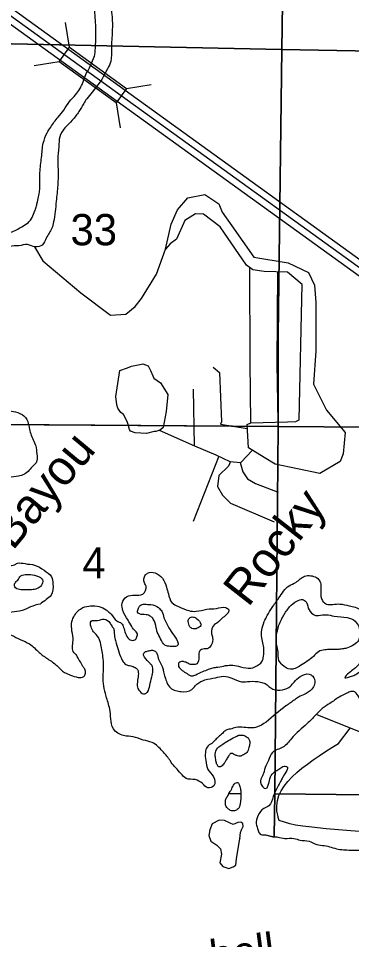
# Model space of a CAD drawing. Extents: x 380424 to 701066, y 1117407 to 1412949.
# Drawn here: x 458914 to 463713, y 1324590 to 1337847 of the extents above; entities that cross this region are included whole.
import ezdxf

# ---------------------------------------------------------------- set-up
doc = ezdxf.new("R2010")
doc.units = 0
for name, color, linetype in [('Bayou and Harbor etc Text', 7, 'Continuous'), ('Bridges and Drawbridges State Highways', 7, 'Continuous'), ('Cities Incorporated Area', 7, 'Continuous'), ('Islands', 7, 'Continuous'), ('Lakes and Ponds', 7, 'Continuous'), ('Narrow Canals', 7, 'Continuous'), ('Narrow River Creek and Branch and Slough', 7, 'Continuous'), ('Narrow River Creek and Branch and Slough Text', 7, 'Continuous'), ('Section Lines', 7, 'Continuous'), ('Section Numbers', 7, 'Continuous'), ('State Roads Related Text', 7, 'Continuous'), ('State Route Divided Highway Outline and Fill', 7, 'Continuous'), ('State Routes Highway Center Lines', 7, 'Continuous'), ('Township  and Range lines', 7, 'Continuous'), ('Wide Rivers and Canals', 7, 'Continuous')]:
    doc.layers.add(name, color=color, linetype=linetype)

msp = doc.modelspace()

# ---------------------------------------------------------------- linework, layer by layer
at = {"layer": 'Bridges and Drawbridges State Highways'}
for p, q in [((459649, 1337431), (459591, 1337788)), ((459499, 1337223), (459142, 1337166)), ((460470, 1336839), (460827, 1336897)), ((460320, 1336632), (460378, 1336274))]:
    msp.add_line(p, q, dxfattribs=at)
msp.add_lwpolyline([(459649, 1337431), (460470, 1336839), (460320, 1336632), (459499, 1337223)], close=True, dxfattribs=at)
at = {"layer": 'Cities Incorporated Area'}
for points in [[(461897, 1328533), (462002, 1328538), (462113, 1328517), (462261, 1328496), (462377, 1328549), (462425, 1328596), (462440, 1328644), (462451, 1328749), (462440, 1328839), (462419, 1328934), (462419, 1329045), (462456, 1329166), (462498, 1329256), (462567, 1329367), (462667, 1329509), (462815, 1329683), (462910, 1329731), (463037, 1329820), (463121, 1329826), (463206, 1329799), (463264, 1329725), (463269, 1329652), (463269, 1329557), (463279, 1329498), (463311, 1329446), (463369, 1329414), (463443, 1329414), (463543, 1329419), (463680, 1329393), (463765, 1329372), (463913, 1329266), (463997, 1329171), (464023, 1329182), (464039, 1329214), (464050, 1329287), (464050, 1329340), (464034, 1329404), (464023, 1329509), (464008, 1329583), (463992, 1329863), (463971, 1330475), (463987, 1330712), (464002, 1330834), (464045, 1330976), (464092, 1331071), (464150, 1331150), (464203, 1331250), (464203, 1331319), (464182, 1331520), (464166, 1331615), (464171, 1331725), (464192, 1331815), (464293, 1331826), (464472, 1331831), (464583, 1331863), (464657, 1331958), (464683, 1332031), (464620, 1332090), (464615, 1332137), (464657, 1332174), (464720, 1332206), (464826, 1332311), (464873, 1332459), (464863, 1332601), (464820, 1332770), (464789, 1332971), (464746, 1333060), (464667, 1333134), (464562, 1333303), (464520, 1333446), (464520, 1333511)], [(456108, 1331224), (456235, 1331076), (456430, 1330913), (456683, 1330691), (456805, 1330549), (457000, 1330343), (457200, 1330158), (457427, 1329995), (457649, 1329868), (457870, 1329741), (458087, 1329715), (458177, 1329757), (458187, 1329805), (458198, 1329915), (458198, 1330000), (458177, 1330095), (458155, 1330169), (458050, 1330364), (457987, 1330475), (457849, 1330617), (457749, 1330749), (457659, 1330865), (457559, 1330987), (457543, 1331087), (457543, 1331203), (457596, 1331261), (457691, 1331272), (457807, 1331240), (457918, 1331256), (458018, 1331287), (458092, 1331256), (458145, 1331187), (458219, 1331177), (458324, 1331240), (458430, 1331303), (458498, 1331435), (458514, 1331546), (458504, 1331572), (458462, 1331657), (458435, 1331731), (458425, 1331841), (458446, 1331963), (458498, 1332068), (458567, 1332148), (458651, 1332195), (458752, 1332200), (458873, 1332184), (458994, 1332126), (459037, 1332074), (459068, 1331958), (459126, 1331783), (459163, 1331694), (459179, 1331583), (459169, 1331451), (459132, 1331414), (459000, 1331287), (458915, 1331261), (458778, 1331240), (458699, 1331229), (458588, 1331192), (458477, 1331150), (458398, 1331113), (458314, 1331039), (458235, 1330939), (458192, 1330865), (458177, 1330786), (458171, 1330717), (458198, 1330633), (458256, 1330543), (458324, 1330448), (458377, 1330369), (458409, 1330285), (458435, 1330206), (458430, 1330068), (458414, 1329968), (458403, 1329868), (458393, 1329762), (458414, 1329736), (458430, 1329683), (458472, 1329667), (458520, 1329662), (458578, 1329704), (458604, 1329746), (458625, 1329794), (458667, 1329889), (458704, 1329952), (458773, 1329973), (458857, 1329984), (458900, 1330005), (459010, 1330000), (459148, 1329979), (459285, 1329905), (459390, 1329810), (459411, 1329710), (459385, 1329546), (459316, 1329483), (459227, 1329419)], [(459227, 1329419), (459089, 1329377), (458968, 1329324), (458820, 1329303), (458710, 1329272), (458604, 1329203), (458641, 1329124), (458725, 1329018), (458815, 1328971), (458942, 1328907), (459074, 1328844), (459211, 1328723), (459338, 1328628), (459469, 1328533), (459580, 1328433), (459665, 1328396), (459775, 1328364), (459855, 1328374), (459881, 1328422), (459870, 1328480), (459844, 1328522), (459823, 1328559), (459760, 1328665), (459749, 1328686), (459717, 1328717), (459702, 1328892), (459686, 1329029), (459686, 1329166), (459723, 1329256), (459844, 1329367), (459955, 1329393), (460076, 1329382), (460177, 1329335), (460219, 1329303), (460240, 1329282), (460250, 1329272), (460330, 1329177), (460398, 1329140), (460430, 1329082), (460456, 1328997), (460509, 1328913), (460578, 1328897), (460604, 1328913), (460625, 1328960), (460630, 1328992), (460609, 1329018), (460546, 1329097), (460493, 1329187), (460419, 1329324), (460409, 1329430), (460472, 1329525), (460588, 1329546), (460704, 1329562), (460752, 1329678), (460736, 1329710), (460720, 1329768), (460736, 1329826), (460773, 1329863), (460884, 1329868), (460989, 1329789), (461047, 1329662), (461074, 1329567), (461126, 1329440), (461221, 1329382), (461369, 1329324), (461475, 1329314), (461628, 1329345), (461765, 1329356), (461902, 1329367), (461944, 1329335), (461923, 1329277), (461860, 1329224), (461770, 1329145), (461739, 1329124), (461696, 1328992), (461712, 1328934), (461691, 1328828), (461633, 1328776), (461549, 1328765), (461512, 1328707), (461512, 1328659), (461485, 1328559), (461432, 1328549), (461380, 1328554), (461327, 1328580), (461279, 1328591), (461227, 1328575), (461221, 1328522), (461274, 1328464), (461343, 1328417), (461417, 1328385), (461469, 1328401), (461570, 1328448), (461654, 1328480), (461717, 1328501), (461786, 1328512), (461897, 1328533)], [(464630, 1329783), (464686, 1329695), (464696, 1329578), (464664, 1329439), (464601, 1329328), (464558, 1329280), (464473, 1329157), (464213, 1328929), (464010, 1328753), (463915, 1328657), (463862, 1328620), (463830, 1328572), (463745, 1328482), (463676, 1328429), (463617, 1328359), (463712, 1328380), (463775, 1328406), (463855, 1328464), (463960, 1328517), (464082, 1328549), (464219, 1328549), (464378, 1328521), (464430, 1328475), (464530, 1328353), (464636, 1328148), (464625, 1328010), (464578, 1327973), (464509, 1328000), (464440, 1328095), (464388, 1328163), (464330, 1328264), (464250, 1328374), (464087, 1328427), (463992, 1328369), (463939, 1328311), (463902, 1328221), (463965, 1328163), (464013, 1328126), (464140, 1328100), (464282, 1328105), (464319, 1328053), (464287, 1328000), (464250, 1327979), (464213, 1327936), (464219, 1327910), (464303, 1327905), (464382, 1327857), (464398, 1327762), (464377, 1327715), (464314, 1327688), (464219, 1327641), (464134, 1327630), (464023, 1327683), (463934, 1327768), (463876, 1327873), (463849, 1327995), (463807, 1328100), (463744, 1328158), (463702, 1328158), (463644, 1328137), (463533, 1328079), (463401, 1327989), (463290, 1327915), (463195, 1327820), (463074, 1327699), (462847, 1327483), (462723, 1327359), (462573, 1327282), (462514, 1327165), (462478, 1327092), (462445, 1326982), (462426, 1326938), (462401, 1326854), (462474, 1326762), (462536, 1326905), (462583, 1326987), (462694, 1327061), (462757, 1327087), (462789, 1327071), (462778, 1327024), (462725, 1326934), (462699, 1326881), (462662, 1326812), (462584, 1326650), (462521, 1326515), (462448, 1326478), (462364, 1326372), (462339, 1326255), (462357, 1326189), (462379, 1326130), (462419, 1326097), (462474, 1326097), (462521, 1326083), (462565, 1326075), (462580, 1326068), (462620, 1326068), (462649, 1326065)], [(462649, 1326065), (462752, 1326046), (462883, 1326046), (462971, 1326021), (463100, 1326005), (463211, 1325958), (463319, 1325943), (463520, 1325892), (463723, 1325878), (463923, 1325873), (464124, 1325863), (464298, 1325852), (464525, 1325826), (464710, 1325810), (465005, 1325810), (465132, 1325831), (465290, 1325842), (465380, 1325820), (465464, 1325778), (465538, 1325694), (465612, 1325667), (465733, 1325725), (465791, 1325752), (465865, 1325762), (466087, 1325762), (466282, 1325762), (466477, 1325757), (466694, 1325741), (466968, 1325773), (467095, 1325805), (467306, 1325842), (467411, 1325831), (467622, 1325805), (467723, 1325826), (467797, 1325921), (467802, 1326053), (467804, 1326173)]]:
    msp.add_spline(points, degree=3, dxfattribs=at)
at = {"layer": 'Islands'}
msp.add_lwpolyline([(461673, 1326171), (461658, 1326087), (461684, 1326006), (461772, 1325948), (461827, 1325896), (461838, 1325820), (461816, 1325695), (461860, 1325640), (461947, 1325615), (462009, 1325637), (462046, 1325662), (462057, 1325750), (462105, 1326046), (462105, 1326039), (462112, 1326131), (462126, 1326171), (462152, 1326215), (462145, 1326262), (462116, 1326281), (462075, 1326277), (462009, 1326244), (461962, 1326266), (461881, 1326306), (461808, 1326310), (461706, 1326255)], close=True, dxfattribs=at)
for points in [[(459116, 1329841), (458936, 1329810), (458915, 1329778), (458894, 1329752), (458873, 1329731), (458857, 1329683), (458873, 1329652), (458952, 1329625), (459053, 1329625), (459105, 1329625), (459184, 1329641), (459237, 1329678), (459264, 1329741), (459264, 1329757), (459232, 1329799), (459116, 1329841)], [(461010, 1329219), (460979, 1329314), (460931, 1329367), (460820, 1329414), (460773, 1329414), (460731, 1329419), (460667, 1329398), (460646, 1329361), (460630, 1329303), (460657, 1329277), (460752, 1329266), (460820, 1329240), (460857, 1329203), (460899, 1329076), (460915, 1329013), (460963, 1328918), (461021, 1328828), (461079, 1328812), (461163, 1328807), (461211, 1328828), (461206, 1328881), (461132, 1328997), (461010, 1329219)], [(461010, 1329219), (460979, 1329314), (460931, 1329367), (460820, 1329414), (460773, 1329414), (460731, 1329419), (460667, 1329398), (460646, 1329361), (460630, 1329303), (460657, 1329277), (460752, 1329266), (460820, 1329240), (460857, 1329203), (460899, 1329076), (460915, 1329013), (460963, 1328918), (461021, 1328828), (461079, 1328812), (461163, 1328807), (461211, 1328828), (461206, 1328881), (461132, 1328997), (461010, 1329219)], [(462657, 1328733), (462667, 1328607), (462715, 1328543), (462831, 1328480), (462899, 1328491), (462979, 1328533), (463074, 1328596), (463163, 1328665), (463237, 1328733), (463327, 1328760), (463406, 1328765), (463491, 1328765), (463564, 1328770), (463628, 1328781), (463723, 1328818), (463802, 1328881), (463828, 1328939), (463834, 1329002), (463765, 1329171), (463649, 1329224), (463464, 1329245), (463348, 1329266), (463237, 1329256), (463195, 1329256), (463158, 1329272), (463089, 1329361), (463058, 1329451), (463006, 1329483), (462926, 1329462), (462820, 1329377), (462731, 1329250), (462704, 1329198), (462667, 1329113), (462646, 1329034), (462630, 1328966), (462625, 1328918), (462657, 1328733)], [(461702, 1327414), (461633, 1327361), (461607, 1327282), (461612, 1327166), (461644, 1327039), (461723, 1326934), (461728, 1326802), (461644, 1326776), (461564, 1326834), (461459, 1326892), (461332, 1326907), (461253, 1326981), (461116, 1327140), (461089, 1327182), (460989, 1327303), (460841, 1327425), (460710, 1327462), (460567, 1327509), (460430, 1327525), (460282, 1327625), (460245, 1327768), (460229, 1327905), (460177, 1328095), (460134, 1328385), (460140, 1328454), (460134, 1328633), (460103, 1328839), (460066, 1328939), (459997, 1329018), (459960, 1329092), (459960, 1329171), (460055, 1329182), (460150, 1329203), (460235, 1329145), (460266, 1329092), (460282, 1329071), (460293, 1329018), (460303, 1328929), (460324, 1328855), (460361, 1328733), (460414, 1328601), (460462, 1328549), (460514, 1328533), (460583, 1328512), (460630, 1328475), (460641, 1328396), (460636, 1328348), (460625, 1328243), (460662, 1328163), (460736, 1328126), (460773, 1328153), (460805, 1328248), (460836, 1328369), (460852, 1328464), (460841, 1328528), (460810, 1328564), (460731, 1328654), (460715, 1328696), (460736, 1328728), (460783, 1328744), (460831, 1328754), (460884, 1328739), (460915, 1328696), (460926, 1328649), (460942, 1328607), (460994, 1328491), (461005, 1328443), (461026, 1328364), (461053, 1328290), (461105, 1328211), (461179, 1328174), (461258, 1328158), (461411, 1328190), (461485, 1328264), (461601, 1328327), (461754, 1328359), (461870, 1328380), (461987, 1328353), (462129, 1328301), (462245, 1328306), (462403, 1328295), (462467, 1328274), (462578, 1328195), (462720, 1328185), (462831, 1328237), (462884, 1328295), (462973, 1328374), (463100, 1328411), (463153, 1328380), (463184, 1328285), (463153, 1328211), (463100, 1328158), (463047, 1328126), (462947, 1328079), (462894, 1328042), (462768, 1327952), (462483, 1327720)], [(461485, 1329208), (461448, 1329229), (461390, 1329224), (461359, 1329182), (461364, 1329150), (461374, 1329108), (461401, 1329076), (461459, 1329060), (461491, 1329071), (461517, 1329087), (461543, 1329108), (461543, 1329131), (461485, 1329208)], [(462483, 1327720), (462345, 1327646), (462277, 1327636), (462045, 1327641), (461971, 1327620), (461897, 1327599), (461855, 1327557), (461797, 1327509), (461754, 1327467), (461702, 1327414)], [(462082, 1327530), (461892, 1327425), (461828, 1327382), (461781, 1327345), (461749, 1327256), (461754, 1327203), (461760, 1327161), (461775, 1327108), (461802, 1327076), (461849, 1327092), (461886, 1327140), (461907, 1327177), (461939, 1327229), (461971, 1327266), (461997, 1327266), (462029, 1327250), (462071, 1327235), (462103, 1327229), (462155, 1327250), (462203, 1327282), (462235, 1327356), (462245, 1327409), (462240, 1327467), (462213, 1327498), (462150, 1327530), (462082, 1327530)], [(462108, 1326538), (462118, 1326717), (462108, 1326776), (462097, 1326807), (462076, 1326849), (462024, 1326828), (461987, 1326760), (461965, 1326723), (461929, 1326659), (461902, 1326612), (461897, 1326543), (461902, 1326517), (461939, 1326469), (461981, 1326443), (462039, 1326448), (462087, 1326480), (462108, 1326538)]]:
    msp.add_spline(points, degree=3, dxfattribs=at)
at = {"layer": 'Lakes and Ponds'}
for points in [[(461115, 1334885), (461204, 1335094), (461354, 1335267), (461601, 1335312), (461803, 1335177), (461848, 1335057), (461990, 1334862), (462305, 1334413), (462799, 1334330), (463091, 1334188), (463181, 1334008), (463196, 1333761), (463196, 1333065), (463166, 1332585), (463353, 1332211), (463622, 1331889), (463592, 1331581), (463547, 1331470), (463255, 1331297), (462612, 1331432), (462454, 1331530), (462230, 1331665), (462207, 1332002), (462260, 1332025), (462791, 1332040), (462911, 1332047), (462956, 1332070), (463001, 1334017), (462791, 1334197), (462454, 1334204), (462290, 1334227), (462200, 1334294), (461818, 1334849), (461579, 1335028), (461466, 1335036), (461309, 1334938), (461189, 1334669), (461100, 1334601), (461032, 1334526)], [(461040, 1332190), (460998, 1331958), (460961, 1331926), (460892, 1331900), (460871, 1331900), (460760, 1331873), (460596, 1331884), (460528, 1331905), (460512, 1331932), (460496, 1332005), (460480, 1332048), (460427, 1332148), (460390, 1332174), (460364, 1332211), (460348, 1332238), (460332, 1332285), (460316, 1332407), (460375, 1332782), (460485, 1332819), (460544, 1332840), (460686, 1332872), (460707, 1332877), (460781, 1332845), (460802, 1332808), (460818, 1332782), (460850, 1332703), (460866, 1332671), (460961, 1332602), (461066, 1332433)]]:
    msp.add_lwpolyline(points, close=True, dxfattribs=at)
at = {"layer": 'Narrow Canals'}
msp.add_line((463523, 1327412), (463694, 1327634), dxfattribs=at)
for points in [[(461802, 1331547), (461431, 1330607)], [(467814, 1326955), (465498, 1327032), (465133, 1327206), (464447, 1327365), (464103, 1327470), (463204, 1327829)], [(463998, 1326129), (463348, 1326182), (463142, 1326208), (463010, 1326224), (462905, 1326235), (462825, 1326256), (462672, 1326303)]]:
    msp.add_lwpolyline(points, dxfattribs=at)
msp.add_spline([(462672, 1326303), (462653, 1326361), (463523, 1327412)], degree=3, dxfattribs=at)
at = {"layer": 'Narrow River Creek and Branch and Slough'}
msp.add_line((461429, 1332512), (461444, 1331698), dxfattribs=at)
for points in [[(459145, 1334561), (459266, 1334360), (459812, 1333896), (460239, 1333574), (460463, 1333589), (460598, 1333701), (460688, 1333814), (460905, 1334166), (461032, 1334526)], [(462260, 1332025), (462252, 1332901), (462245, 1334261)], [(462657, 1332036), (462642, 1332879), (462649, 1334200)], [(461721, 1332827), (461811, 1332752), (461841, 1332040), (461826, 1332010), (462211, 1331947)], [(460941, 1331919), (461451, 1331695), (461758, 1331568), (461960, 1331470), (462118, 1331455), (462286, 1331632)], [(461967, 1331470), (461938, 1331403), (461803, 1331268), (461781, 1331111), (461856, 1330984), (461968, 1330871), (462597, 1330602)], [(462110, 1331456), (462148, 1331321), (462215, 1331223), (462327, 1331156), (462657, 1331029)]]:
    msp.add_lwpolyline(points, dxfattribs=at)
at = {"layer": 'Section Lines'}
msp.add_line((461947, 1326692), (462117, 1326691), dxfattribs=at)
for points in [[(462784, 1342680), (462706, 1337400), (457436, 1337512), (457525, 1342809), (462779, 1342686)], [(468083, 1342564), (467996, 1337306), (462706, 1337400), (462784, 1342680)], [(457374, 1332012), (457412, 1335643), (457436, 1337512), (462706, 1337400), (462657, 1333283), (462653, 1331974)], [(467996, 1337306), (467925, 1333262), (467922, 1331936), (462653, 1331974), (462657, 1333283), (462657, 1333287), (462706, 1337400)], [(467922, 1331936), (467906, 1326629), (462607, 1326689), (462653, 1331970), (462653, 1331974)]]:
    msp.add_lwpolyline(points, close=True, dxfattribs=at)
for points in [[(457359, 1330037), (457374, 1332012), (462653, 1331974), (462607, 1326689), (462602, 1326689)], [(462602, 1326689), (462607, 1326689), (462599, 1326068)], [(462599, 1326068), (462607, 1326689), (467906, 1326629), (467891, 1325464)]]:
    msp.add_lwpolyline(points, dxfattribs=at)
at = {"layer": 'State Route Divided Highway Outline and Fill'}
msp.add_lwpolyline([(449994, 1344364), (454985, 1340762), (460367, 1336878), (464957, 1333566), (465504, 1333171), (465876, 1332927), (466264, 1332719), (467332, 1332321), (467912, 1332128), (493014, 1331939), (493011, 1331739), (467878, 1331928), (467266, 1332132), (466182, 1332537), (465774, 1332755), (465391, 1333007), (464840, 1333404), (460250, 1336716), (454868, 1340600), (449885, 1344196)], dxfattribs=at)
at = {"layer": 'State Routes Highway Center Lines'}
msp.add_lwpolyline([(493112, 1331838), (467895, 1332028), (467299, 1332227), (466223, 1332628), (465825, 1332841), (465448, 1333089), (464899, 1333485), (460309, 1336797), (454927, 1340681), (449940, 1344280)], dxfattribs=at)
at = {"layer": 'Township  and Range lines'}
for p, q in [((457374, 1332012), (462653, 1331974)), ((462653, 1331974), (467922, 1331936))]:
    msp.add_line(p, q, dxfattribs=at)
at = {"layer": 'Wide Rivers and Canals'}
for points in [[(459831, 1336896), (459892, 1337056), (459910, 1337084), (459920, 1337099), (459938, 1337135), (459996, 1337269)], [(460198, 1337123), (460135, 1337005), (460115, 1336969), (460107, 1336953), (460099, 1336941), (460091, 1336933), (459977, 1336785)]]:
    msp.add_lwpolyline(points, dxfattribs=at)
for points in [[(459996, 1337269), (460008, 1337298), (460023, 1337419), (460029, 1337530), (459976, 1338633), (460008, 1338835), (460100, 1339014), (460544, 1339617), (460874, 1340098), (461095, 1340343), (462715, 1341602), (463997, 1342522), (464155, 1342607), (464366, 1342728), (467873, 1343765)], [(467873, 1343606), (464430, 1342527), (464129, 1342374), (463950, 1342253), (461464, 1340294), (461258, 1340112), (461109, 1339930), (460423, 1338997), (460299, 1338841), (460266, 1338740), (460242, 1338600), (460224, 1338195), (460261, 1337899), (460266, 1337662), (460255, 1337418), (460244, 1337229), (460198, 1337123)], [(459053, 1334907), (459100, 1334960), (459141, 1335054), (459167, 1335116), (459182, 1335181), (459206, 1335277), (459224, 1335433), (459224, 1335627), (459247, 1335845), (459273, 1336052), (459328, 1336200), (459380, 1336284), (459486, 1336427), (459569, 1336528), (459650, 1336650), (459738, 1336749), (459798, 1336834), (459831, 1336896)], [(459977, 1336785), (459899, 1336689), (459855, 1336624), (459787, 1336507), (459689, 1336382), (459510, 1336145), (459496, 1336000), (459480, 1335815), (459485, 1335678), (459480, 1335446), (459459, 1335219), (459443, 1335066), (459422, 1334918), (459396, 1334828), (459316, 1334686), (459258, 1334586), (459158, 1334559), (459047, 1334591), (458921, 1334575), (458789, 1334564), (458704, 1334522), (458609, 1334464), (458504, 1334385), (458303, 1334306), (458187, 1334243), (458050, 1334169), (457913, 1334105), (457791, 1334053), (457665, 1333857), (455996, 1331795)], [(455917, 1332113), (455955, 1332174), (457126, 1333551), (457248, 1333694), (457417, 1333863), (457580, 1334042), (457733, 1334184), (457897, 1334343), (458108, 1334475), (458266, 1334586), (458483, 1334649), (458688, 1334733), (458805, 1334770), (458963, 1334849), (459053, 1334907)]]:
    msp.add_spline(points, degree=3, dxfattribs=at)

# ---------------------------------------------------------------- texts
at = {"layer": 'Bayou and Harbor etc Text'}
msp.add_text('Bayou', height=500, rotation=50.1587, dxfattribs=at).set_placement((458833, 1330177))
at = {"layer": 'Narrow River Creek and Branch and Slough Text'}
msp.add_text('Rocky', height=500, rotation=52.1021, dxfattribs=at).set_placement((462223, 1329361))
at = {"layer": 'Section Numbers'}
for s, p in [('33', (459665, 1334582)), ('4', (459836, 1329787))]:
    msp.add_text(s, height=450, dxfattribs=at).set_placement(p)
at = {"layer": 'State Roads Related Text'}
msp.add_text('Campbell', height=450, rotation=7.4589, dxfattribs=at).set_placement((460110, 1323917))

doc.saveas('drawing.dxf')
